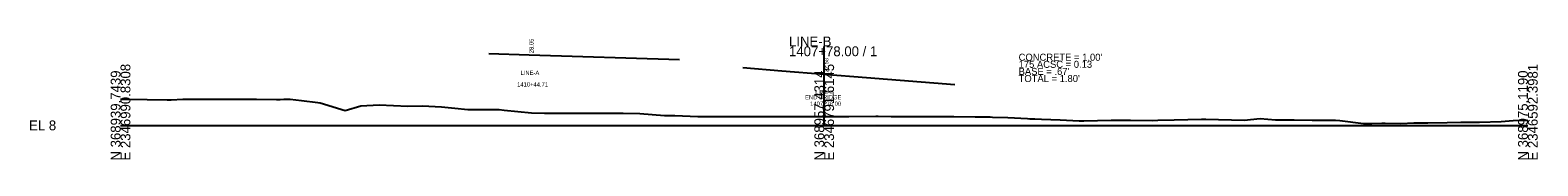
# Model space of a CAD drawing. Extents: x -26 to 2400, y -10 to 9525.
# Drawn here: x -25.7 to 402.8, y 9490.3 to 9525.3 of the extents above; entities that cross this region are included whole.
import ezdxf

# ---------------------------------------------------------------- set-up
doc = ezdxf.new("R2010")
doc.units = 0
for name, color, linetype in [('RD_GPK_XS_Cell', 7, 'Continuous'), ('RD_XS_Bridge', 7, 'Continuous'), ('RD_XS_ExGround', 7, 'Continuous'), ('RD_XS_Pave', 7, 'Continuous'), ('RD_XS_PaveShd', 7, 'Continuous'), ('RD_XS_TieSlope', 7, 'Continuous'), ('RD_XS_TX_Elev_EX', 7, 'Continuous'), ('RD_XS_TX_Elev_PR', 7, 'Continuous'), ('RD_XS_TX_Station', 7, 'Continuous')]:
    doc.layers.add(name, color=color, linetype=linetype)

msp = doc.modelspace()

# ---------------------------------------------------------------- linework, layer by layer
at = {"layer": 'RD_GPK_XS_Cell'}
for p, q in [((200, 9500), (200, 9522.46)), ((0, 9500), (200, 9500)), ((200, 9500), (400, 9500))]:
    msp.add_line(p, q, dxfattribs=at)
at = {"layer": 'RD_XS_Bridge'}
for p, q in [((104.65, 9520.39), (116.18, 9520.05)), ((116.18, 9520.05), (158.83, 9518.77))]:
    msp.add_line(p, q, dxfattribs=at)
at = {"layer": 'RD_XS_ExGround'}
msp.add_lwpolyline([(0, 9507.45), (1.39, 9507.43), (1.89, 9507.43), (13.26, 9507.27), (14.39, 9507.28), (17.68, 9507.44), (19, 9507.43), (24.44, 9507.45), (25.27, 9507.49), (38.6, 9507.48), (44.37, 9507.38), (45.38, 9507.32), (46.39, 9507.43), (48.18, 9507.43), (51.42, 9507.07), (56.04, 9506.5), (56.7, 9506.37), (63.87, 9504.23), (68.25, 9505.57), (73.5, 9505.83), (81.69, 9505.5), (85.87, 9505.59), (91.2, 9505.26), (94.98, 9504.9), (98.72, 9504.49), (105.27, 9504.51), (106.82, 9504.52), (107.59, 9504.49), (109.04, 9504.33), (116.79, 9503.55), (120.49, 9503.5), (130.89, 9503.43), (131.82, 9503.43), (132.63, 9503.43), (142.88, 9503.44), (147.59, 9503.38), (154.61, 9502.81), (157.58, 9502.84), (164.08, 9502.55), (172.58, 9502.5), (179.29, 9502.5), (179.71, 9502.5), (181.45, 9502.5), (190.68, 9502.48), (192.84, 9502.49), (199.44, 9502.5), (200, 9502.5), (204.86, 9502.5), (207, 9502.49), (214.72, 9502.61), (215.38, 9502.58), (219, 9502.57), (222.58, 9502.52), (223.63, 9502.51), (235.72, 9502.5), (236.47, 9502.49), (236.89, 9502.5), (242.95, 9502.45), (247.13, 9502.39), (247.88, 9502.37), (252.23, 9502.21), (257.77, 9501.95), (258.46, 9501.83), (259.17, 9501.88), (259.89, 9501.89), (261.78, 9501.78), (267.09, 9501.54), (272.5, 9501.26), (273.24, 9501.26), (273.77, 9501.26), (281.6, 9501.44), (284.74, 9501.5), (287.02, 9501.44), (293.22, 9501.42), (294.86, 9501.5), (299.5, 9501.62), (307.23, 9501.75), (307.71, 9501.74), (308.44, 9501.74), (319.41, 9501.5), (323.9, 9501.92), (328.31, 9501.55), (331.23, 9501.56), (333.54, 9501.55), (338.74, 9501.49), (344.39, 9501.49), (345.35, 9501.5), (346.58, 9501.35), (353.32, 9500.57), (355.63, 9500.54), (358.53, 9500.59), (359.43, 9500.59), (363.88, 9500.58), (367.62, 9500.69), (371.56, 9500.7), (377.05, 9500.83), (380.99, 9500.94), (386.3, 9500.9), (392.38, 9501.11), (395.87, 9501.42), (400, 9501.45)], dxfattribs=at)
at = {"layer": 'RD_XS_Pave'}
for p, q in [((188, 9515.54), (200, 9514.58)), ((200, 9514.58), (212, 9513.62))]:
    msp.add_line(p, q, dxfattribs=at)
at = {"layer": 'RD_XS_PaveShd'}
for p, q in [((176.88, 9516.43), (188, 9515.54)), ((212, 9513.62), (237.13, 9511.61))]:
    msp.add_line(p, q, dxfattribs=at)

# ---------------------------------------------------------------- texts
at = {"layer": 'RD_GPK_XS_Cell'}
for s, p in [('1407+78.00 / 1', (190, 9519.66)), ('LINE-B', (190, 9522.46)), ('EL 8', (-26, 9498.6))]:
    msp.add_text(s, height=2.8, dxfattribs=at).set_placement(p)
for s, p in [('N 368939.7439', (0, 9490)), ('E 2346990.8308', (2.8, 9490)), ('N 368957.4314', (200, 9490)), ('E 2346791.6145', (202.8, 9490)), ('N 368975.1190', (400, 9490)), ('E 2346592.3981', (402.8, 9490))]:
    msp.add_text(s, height=2.8, rotation=90, dxfattribs=at).set_placement(p)
at = {"layer": 'RD_XS_TieSlope'}
for s, p in [("CONCRETE = 1.00'", (255.26, 9518.37)), ('175 ACSC = 0.13', (255.26, 9516.36)), ("TOTAL = 1.80'", (255.26, 9512.32)), ("BASE = .67'", (255.26, 9514.34))]:
    msp.add_text(s, height=2, dxfattribs=at).set_placement(p)
at = {"layer": 'RD_XS_TX_Elev_EX'}
msp.add_text('10.50', height=1, rotation=90, dxfattribs=at).set_placement((200.5, 9502.5))
at = {"layer": 'RD_XS_TX_Elev_PR'}
for s, p in [(' 28.05', (117.38, 9520.05)), (' 22.58', (201.2, 9514.58))]:
    msp.add_text(s, height=1.2, rotation=90, dxfattribs=at).set_placement(p)
at = {"layer": 'RD_XS_TX_Station'}
for s, p in [('LINE-A', (113.68, 9514.35)), ('1410+44.71', (112.71, 9511.05)), ('LINE-B', (197.43, 9508.88)), ('END BRIDGE', (194.58, 9507.39)), ('1407+78.00', (196.01, 9505.58))]:
    msp.add_text(s, height=1.2, dxfattribs=at).set_placement(p)

doc.saveas('drawing.dxf')
